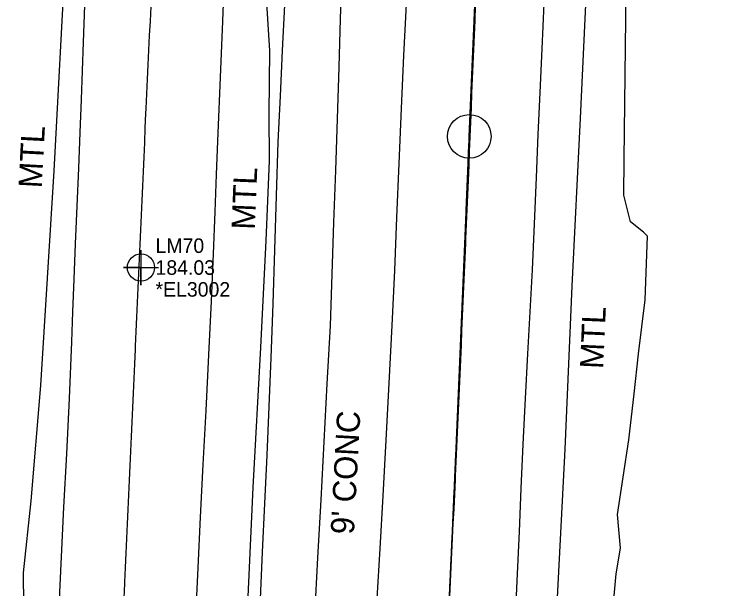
# Model space of a CAD drawing. Extents: x 2262665 to 2270527, y 505476 to 514960.
# Drawn here: x 2266242.3 to 2266364.6, y 510262.5 to 510361.1 of the extents above; entities that cross this region are included whole.
import ezdxf

# ---------------------------------------------------------------- set-up
doc = ezdxf.new("R2010")
doc.units = 0
for name, color, linetype in [('Exist Guardrail', 7, 'Continuous'), ('Exist Guardrail Text', 7, 'Continuous'), ('Exist Horizontal Alignment', 7, 'Continuous'), ('Exist Roads EOP', 7, 'Continuous'), ('Exist Roads EOT', 7, 'Continuous'), ('Exist Roads EOT Cogo Comment', 7, 'Continuous'), ('Exist Roads EOT Cogo Elevation', 7, 'Continuous'), ('Exist Roads EOT Cogo Number', 7, 'Continuous'), ('Exist Roads EOT Cogo Point CELL', 7, 'Continuous'), ('Exist Structure Minor Paved Ditch or Gutter', 7, 'Continuous'), ('Exist Structure Minor Paved Ditch or Gutter Text', 7, 'Continuous'), ('Exist Vegetation Hedge Row', 7, 'Continuous')]:
    doc.layers.add(name, color=color, linetype=linetype)

msp = doc.modelspace()

# ---------------------------------------------------------------- linework, layer by layer
at = {"layer": 'Exist Guardrail'}
for points in [[(2266340.22, 510511.07), (2266339.26, 510484.64), (2266338.88, 510468.22), (2266339.23, 510456.4), (2266340.62, 510433.45), (2266341.52, 510418.91), (2266341.98, 510406.29), (2266341.94, 510393.06), (2266341.16, 510377.42), (2266339.55, 510343.25), (2266338.13, 510314.39), (2266336.91, 510286.44), (2266335.26, 510254.31), (2266334.39, 510233.28)], [(2266284.64, 510431.58), (2266284.07, 510415.44), (2266283.84, 510408.62), (2266284.03, 510397.07), (2266284.4, 510385.09), (2266285.12, 510372.08), (2266285.53, 510364.91), (2266285.96, 510358.39), (2266286.15, 510354.86), (2266286.07, 510344), (2266286.13, 510335.93), (2266285.57, 510322.27), (2266284.61, 510303.87), (2266283.3, 510279.81), (2266282.14, 510254.84), (2266280.79, 510232.67)], [(2266242.31, 510234.33), (2266243.95, 510259.62), (2266243.88, 510265.17), (2266245.25, 510277.54), (2266246.86, 510297.33), (2266249.2, 510334.2), (2266251.2, 510371.8), (2266251.53, 510388.08)]]:
    msp.add_lwpolyline(points, dxfattribs=at)
at = {"layer": 'Exist Horizontal Alignment'}
msp.add_line((2266320.5, 510340.11), (2266385.32, 511909.14), dxfattribs=at)
msp.add_circle((2266320.5, 510340.11), 3.75, dxfattribs=at)
msp.add_arc((2263773.45, 510337.89), 2625, 349.59137, 358.85635, dxfattribs=at)
msp.add_spline([(2266309.93, 510140.4), (2266310.13, 510143.09), (2266310.34, 510145.79), (2266310.53, 510148.48), (2266310.73, 510151.18), (2266310.93, 510153.87), (2266311.12, 510156.57), (2266311.31, 510159.27), (2266311.49, 510161.96), (2266311.68, 510164.66), (2266311.86, 510167.36), (2266312.04, 510170.05), (2266312.22, 510172.75), (2266312.4, 510175.45), (2266312.57, 510178.14), (2266312.74, 510180.84), (2266312.91, 510183.54), (2266313.08, 510186.23), (2266313.25, 510188.93), (2266313.41, 510191.63), (2266313.57, 510194.33), (2266313.73, 510197.03), (2266313.89, 510199.72), (2266314.05, 510202.42), (2266314.21, 510205.12), (2266314.36, 510207.82), (2266314.51, 510210.52), (2266314.66, 510213.22), (2266314.81, 510215.91), (2266314.96, 510218.61), (2266315.1, 510221.31), (2266315.25, 510224.01), (2266315.39, 510226.71), (2266315.53, 510229.41), (2266315.67, 510232.11), (2266315.81, 510234.81), (2266315.94, 510237.51), (2266316.08, 510240.21), (2266316.21, 510242.9), (2266316.35, 510245.6), (2266316.48, 510248.3), (2266316.61, 510251), (2266316.74, 510253.7), (2266316.87, 510256.4), (2266317, 510259.1), (2266317.12, 510261.8), (2266317.25, 510264.5), (2266317.37, 510267.2), (2266317.5, 510269.9), (2266317.62, 510272.6), (2266317.74, 510275.3), (2266317.86, 510278), (2266317.98, 510280.7), (2266318.1, 510283.4), (2266318.22, 510286.1), (2266318.34, 510288.8), (2266318.45, 510291.5), (2266318.57, 510294.2), (2266318.69, 510296.9), (2266318.8, 510299.6), (2266318.92, 510302.3), (2266319.03, 510305), (2266319.15, 510307.7), (2266319.26, 510310.4), (2266319.37, 510313.1), (2266319.49, 510315.8), (2266319.6, 510318.5), (2266319.71, 510321.2), (2266319.83, 510323.9), (2266319.94, 510326.61), (2266320.05, 510329.31), (2266320.16, 510332.01), (2266320.27, 510334.71), (2266320.38, 510337.41), (2266320.5, 510340.11)], degree=3, dxfattribs=at)
at = {"layer": 'Exist Roads EOP'}
for points in [[(2266278.4, 510367.5), (2266278.1, 510359.88), (2266277.7, 510350.22), (2266277.3, 510340.71), (2266277.02, 510333.55), (2266276.77, 510327.17), (2266276.48, 510319.98), (2266276.13, 510311.85), (2266275.69, 510302.64), (2266275.21, 510293.04), (2266274.74, 510283.76), (2266274.28, 510274.77), (2266273.87, 510266.05), (2266273.46, 510257.64)], [(2266333.3, 510362.91), (2266332.96, 510355.16), (2266332.63, 510347.67), (2266332.3, 510340.43), (2266331.98, 510333.04), (2266331.64, 510325.11), (2266331.29, 510317.23), (2266330.91, 510309.98), (2266330.52, 510302.79), (2266330.11, 510295.1), (2266329.71, 510287.27), (2266329.38, 510279.66), (2266329.06, 510272.26), (2266328.72, 510265.01), (2266328.36, 510257.52)], [(2266254.36, 510362.59), (2266254.16, 510356.28), (2266253.81, 510346.44), (2266253.6, 510340.76), (2266253.35, 510334.67), (2266253.08, 510328.15), (2266252.81, 510321.65), (2266252.57, 510315.6), (2266252.34, 510310), (2266252.14, 510304.85), (2266251.74, 510295.11), (2266251.27, 510285.59), (2266250.8, 510276.47), (2266250.39, 510267.93), (2266249.99, 510259.4)], [(2266304.68, 510260.76), (2266305.18, 510269.36), (2266305.69, 510278.38), (2266306.22, 510287.97), (2266306.74, 510297.77), (2266307.24, 510307.63), (2266307.69, 510317.1), (2266308.08, 510326.19), (2266308.47, 510335.45), (2266308.88, 510344.89), (2266309.28, 510354), (2266309.69, 510362.79)]]:
    msp.add_lwpolyline(points, dxfattribs=at)
at = {"layer": 'Exist Roads EOT'}
for points in [[(2266261.19, 510260.86), (2266261.31, 510263.36), (2266261.32, 510263.6), (2266261.43, 510266.09), (2266261.55, 510268.59), (2266261.66, 510271.09), (2266261.78, 510273.58), (2266261.89, 510276.08), (2266262.01, 510278.58), (2266262.12, 510281.08), (2266262.23, 510283.57), (2266262.35, 510286.07), (2266262.46, 510288.57), (2266262.58, 510291.06), (2266262.69, 510293.56), (2266262.81, 510296.06), (2266262.92, 510298.56), (2266263.03, 510301.05), (2266263.15, 510303.55), (2266263.17, 510304.11), (2266263.29, 510306.6), (2266263.4, 510309.1), (2266263.51, 510311.6), (2266263.62, 510314.1), (2266263.73, 510316.59), (2266263.84, 510319.09), (2266263.95, 510321.59), (2266264.06, 510324.09), (2266264.17, 510326.58), (2266264.29, 510329.08), (2266264.4, 510331.58), (2266264.51, 510334.07), (2266264.62, 510336.57), (2266264.73, 510339.07), (2266264.84, 510341.57), (2266264.95, 510344.06), (2266264.99, 510344.92), (2266265.11, 510347.42), (2266265.23, 510349.92), (2266265.34, 510352.41), (2266265.46, 510354.91), (2266265.58, 510357.41), (2266265.7, 510359.9), (2266265.82, 510362.4)], [(2266321.53, 510362.52), (2266321.43, 510360.02), (2266321.33, 510357.52), (2266321.22, 510355.03), (2266321.12, 510352.53), (2266321.02, 510350.03), (2266320.91, 510347.53), (2266320.81, 510345.04), (2266320.71, 510342.54), (2266320.6, 510340.04), (2266320.5, 510337.54), (2266320.4, 510335.04), (2266320.29, 510332.55), (2266320.19, 510330.05), (2266320.08, 510327.55), (2266319.98, 510325.05), (2266319.88, 510322.56), (2266319.84, 510321.75), (2266319.73, 510319.26), (2266319.63, 510316.76), (2266319.52, 510314.26), (2266319.41, 510311.76), (2266319.3, 510309.27), (2266319.19, 510306.77), (2266319.08, 510304.27), (2266318.97, 510301.77), (2266318.86, 510299.28), (2266318.75, 510296.78), (2266318.64, 510294.28), (2266318.53, 510291.78), (2266318.42, 510289.29), (2266318.31, 510286.79), (2266318.21, 510284.29), (2266318.1, 510281.79), (2266318.07, 510281.15), (2266317.95, 510278.65), (2266317.82, 510276.16), (2266317.7, 510273.66), (2266317.58, 510271.16), (2266317.46, 510268.67), (2266317.33, 510266.17), (2266317.21, 510263.67), (2266317.09, 510261.18)]]:
    msp.add_lwpolyline(points, dxfattribs=at)
at = {"layer": 'Exist Roads EOT Cogo Point CELL'}
msp.add_lwpolyline([(2266264.09, 510320.6), (2266264.09, 510314.6), (2266264.09, 510317.6), (2266261.09, 510317.6), (2266267.09, 510317.6)], dxfattribs=at)
msp.add_circle((2266264.09, 510317.6), 2.34, dxfattribs=at)
at = {"layer": 'Exist Structure Minor Paved Ditch or Gutter'}
for points in [[(2266298.58, 510368.6), (2266298.34, 510360.31), (2266298.09, 510352.02), (2266297.79, 510343.13), (2266297.49, 510334.24), (2266297.19, 510325.35), (2266296.89, 510316.46), (2266296.59, 510307.57), (2266296.05, 510297.62), (2266295.52, 510287.66), (2266294.98, 510277.7), (2266294.45, 510267.75), (2266293.92, 510257.79)], [(2266284.56, 510259.4), (2266285, 510268.73), (2266285.38, 510277.07), (2266285.75, 510285.41), (2266286.12, 510293.75), (2266286.49, 510302.09), (2266286.79, 510311.36), (2266287.09, 510320.64), (2266287.39, 510329.91), (2266287.69, 510339.18), (2266288.06, 510347.01), (2266288.43, 510354.84), (2266288.8, 510362.66)]]:
    msp.add_lwpolyline(points, dxfattribs=at)
at = {"layer": 'Exist Vegetation Hedge Row'}
msp.add_lwpolyline([(2266345.24, 510259.36), (2266345.73, 510265.01), (2266346.48, 510269.45), (2266345.97, 510275.19), (2266347.94, 510288.03), (2266348.82, 510295.93), (2266349.57, 510302.81), (2266350.72, 510312.06), (2266351.1, 510323.01), (2266350.46, 510323.66), (2266348.19, 510325.46), (2266347.05, 510330), (2266347.14, 510336.13), (2266347.46, 510365.17), (2266348.15, 510368.99), (2266348.66, 510387.24), (2266350.43, 510399.61), (2266350.71, 510424.18), (2266351.87, 510429.54), (2266353.23, 510430.97), (2266355.6, 510431.45), (2266358.66, 510432.1), (2266361.21, 510432.97), (2266363.38, 510432.9)], dxfattribs=at)

# ---------------------------------------------------------------- texts
at = {"layer": 'Exist Guardrail Text'}
for rotation, p in [(86.9493, (2266247.03, 510331.16)), (87.6397, (2266283.64, 510324.04)), (87.4988, (2266343.51, 510300.14))]:
    msp.add_text('MTL', height=4, rotation=rotation, dxfattribs=at).set_placement(p)
at = {"layer": 'Exist Roads EOT Cogo Comment'}
msp.add_text('*EL3002', height=2.5, dxfattribs=at).set_placement((2266266.59, 510312.6))
at = {"layer": 'Exist Roads EOT Cogo Elevation'}
msp.add_text('184.03', height=2.5, dxfattribs=at).set_placement((2266266.59, 510316.35))
at = {"layer": 'Exist Roads EOT Cogo Number'}
msp.add_text('LM70', height=2.5, dxfattribs=at).set_placement((2266266.59, 510320.1))
at = {"layer": 'Exist Structure Minor Paved Ditch or Gutter Text'}
msp.add_text("9' CONC", height=4, rotation=86.9286, dxfattribs=at).set_placement((2266300.67, 510271.71))

doc.saveas('drawing.dxf')
